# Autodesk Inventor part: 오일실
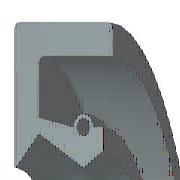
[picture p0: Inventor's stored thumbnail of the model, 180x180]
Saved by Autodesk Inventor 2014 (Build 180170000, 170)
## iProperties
Created: 2009-02
Part Number: 오일실
Material: 고무
Description: 오일-실
Document SubType Name: Modeling
Standard: KS B 2804
Designer: SeoGD™
Standards Organization: KS
Language: ko-KR
Size Designation: D - 10 20 7
Categories: <MemberInstance><Categories><Category DisplayName="샤프트 부품" InternalName="7f7aeb1f-a693-4053-b835-cee3144e0d98" Mnemonic="SHFT"><Category DisplayName="실링" Intern
Density: 0.93 g/cm^3
Appearance: 고무 - 검은색 - 버전 1.1
IsCustomPart: 0
Author: SeoGD™
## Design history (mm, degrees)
revolve "본체" stored, may be unused: angle "d17" = 90 deg
revolve "스프링1" stored, may be unused: angle "d18" = 90 deg
body "Solid1"
sketch "스케치1"
  geometry: L1 (0, 10)-(7, 10); L2 (7, 8.25)-(1.75, 8.25); L3 (1.75, 6.75)-(4.9, 5); L4 (4.9, 5)-(0, 5); L5 (0, 0)-(9.586, 0) reference; L6 (4.9, 5)-(6.3, 5.875); L7 (0, 18)-(0, -3) reference; L8 (-1.941, 0)-(11.507, 0) reference; L9 (4.2, 7.1)-(1.75, 7.59); L10 (1.75, 7.59)-(1.75, 8.25); L11 (0, 10)-(0, 5.088); L12 (4.9, 5)-(0, 5); L13 (1.75, 6.75)-(0.152, 5.028); L14 (7, 10)-(7, 8.25); L15 (5.6, 7.1)-(6.3, 7.1); L16 (6.3, 7.1)-(6.3, 5.875); C1 r 0.455 at (4.9, 7.1); A1 r 0.7 centre (4.9, 7.1) between (5.6, 7.1) and (4.2, 7.1); A2 r 0.088 centre (0.088, 5.088) between (0, 5.088) and (0.152, 5.028); 1 further point
  constraints: 28 end point, 5 horizontal alignment, 5 point on line, 4 point on circle, 4 vertical alignment, 3 centre point, 3 tangent, 2 collinear, 2 horizontal, 2 perpendicular, 1 coincident, 1 parallel
  dimensions: "d0" = 20 diameter of L1 L5 (= SD2); "d1" = 1.75 distance of L1.end L2.start (= SD); "d2" = 0.91 diameter of C1 (= SPDI); "d3" = 1.4 diameter of A1 (= SPDA); "d4" = 10 diameter of L3.end L5 (= NND); "d5" = 13.5 diameter of L3.start L5 (= TKDM); "d7" = 15.18 diameter of L9.end L5 (= TKDM + 0.24 x SWDT); "d8" = 1.75 distance between parallel lines of L11 L10 (= SD); "d9" = 4.9 distance from line of L11 C1.centre (= SPDST); "d10" = 14.2 diameter of C1.centre L5 (= HLDM); "d11" = 0.0875 radius of A2 (= 0.25 x LAB); "d12" = 6.3 distance between parallel lines of L11 L16 (= SDI); "d13" = 11.75 diameter of L6.end L5 (= ABDM); "d14" = 7 distance from line of L11 L1.end (= SWDT)
fillet "모깎기1" dims "d6" = 0.3 (= RR)
other parameters: "SD2" = 20 [user parameter; used in 1 equation term], "SWDT" = 7 [user parameter; used in 2 equation terms], "RR" = 0.3 [user parameter; used in 1 equation term], "SD" = 1.75 [user parameter; used in 2 equation terms], "NND" = 10 [user parameter; used in 1 equation term], "SPDA" = 1.4 [user parameter; used in 1 equation term], "SPDI" = 0.91 [user parameter; used in 1 equation term], "TKDM" = 13.5 [user parameter; used in 2 equation terms], "HLDM" = 14.2 [user parameter; used in 1 equation term], "ABDM" = 11.75 [user parameter; used in 1 equation term], "SDI" = 6.3 [user parameter; used in 1 equation term], "SPDST" = 4.9 [user parameter; used in 1 equation term], "LAB" = 0.35 [user parameter; used in 1 equation term], "d15" = 0, "d16" = 0, "d19" = 0
